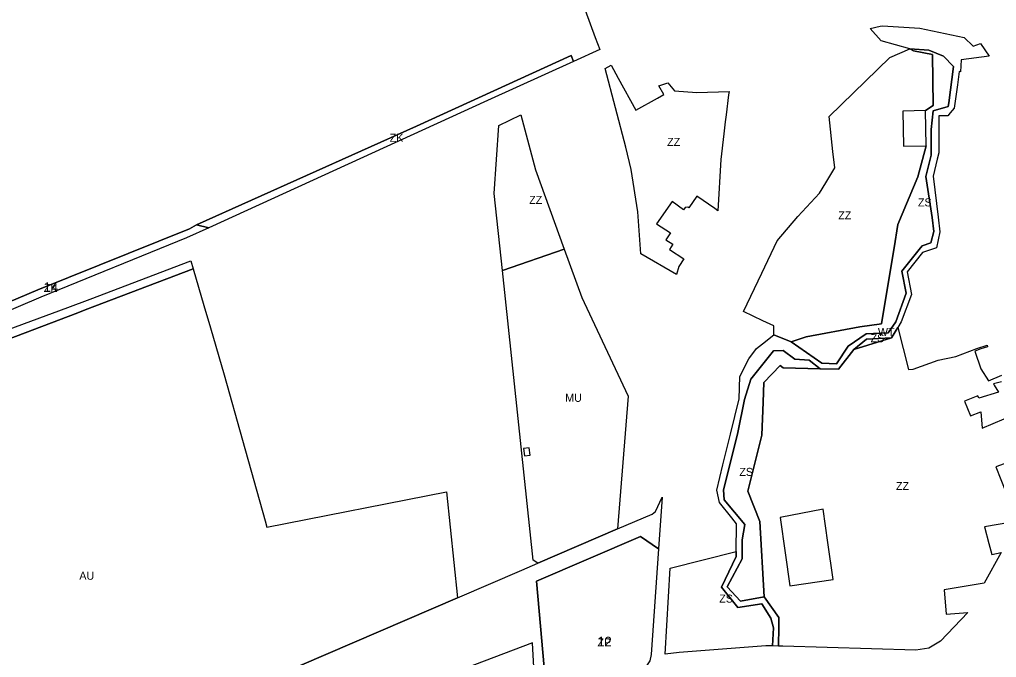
# Model space of a CAD drawing. Extents: x -522079 to -518833, y -1142398 to -1139961.
# Drawn here: x -521001 to -520390, y -1141186 to -1140787 of the extents above; entities that cross this region are included whole.
import ezdxf

# ---------------------------------------------------------------- set-up
doc = ezdxf.new("R2010")
doc.units = 0
for name, color, linetype in [('90640013', 7, 'Continuous'), ('90660013', 7, 'Continuous'), ('90670013', 7, 'Continuous'), ('90680023', 7, 'Continuous'), ('90710013', 7, 'Continuous'), ('90710023', 7, 'Continuous'), ('90750013', 7, 'Continuous'), ('90830013', 7, 'Continuous'), ('ID_navrh', 7, 'Continuous')]:
    doc.layers.add(name, color=color, linetype=linetype)

msp = doc.modelspace()

# ---------------------------------------------------------------- linework, layer by layer
at = {"layer": '90640013'}
msp.add_lwpolyline([(-520536.52, -1140989.65), (-520529.52, -1140984.06), (-520518.62, -1140988.49), (-520499.42, -1141001.88), (-520490.41, -1141002.21), (-520483.03, -1140991.17), (-520471.76, -1140983.46), (-520458.05, -1140982.9), (-520453.28, -1140975.93), (-520446.79, -1140958), (-520449.47, -1140944.32), (-520438.64, -1140930.72), (-520436.87, -1140928.43), (-520431.36, -1140926.59), (-520429.5, -1140919.57), (-520430.59, -1140910.8), (-520434.57, -1140885.18), (-520431.14, -1140872), (-520431.21, -1140855.94), (-520429.98, -1140844.23), (-520420.46, -1140841.58), (-520420.15, -1140839.19), (-520417.22, -1140816.48), (-520423.57, -1140810.07), (-520432.63, -1140806.38), (-520444.45, -1140805.57), (-520462.48, -1140800.42), (-520469.2, -1140792.72), (-520463.08, -1140791.37), (-520461.64, -1140791.05), (-520438.34, -1140792.64), (-520410.6, -1140798.4), (-520404.93, -1140803.86), (-520400.31, -1140802.09), (-520394.93, -1140810.08), (-520412.34, -1140812.28), (-520412.85, -1140819.83), (-520413.68, -1140819.71), (-520414.81, -1140828.01), (-520416.81, -1140842.62), (-520419.27, -1140845.56), (-520420.69, -1140847.27), (-520426.43, -1140847.27), (-520426.37, -1140870.34), (-520427.4, -1140874.32), (-520429.99, -1140884.98), (-520426.8, -1140910.65), (-520425.67, -1140919.72), (-520427.82, -1140929.68), (-520436.62, -1140932.6), (-520446.27, -1140944.76), (-520443.57, -1140958.81), (-520449.86, -1140976.07), (-520451.99, -1140979.48), (-520456.05, -1140986), (-520471.51, -1140986.91), (-520479.55, -1140993.19), (-520489.07, -1141005.5), (-520500.6, -1141005.26), (-520507.31, -1140999.82), (-520516.37, -1140999.34), (-520523.73, -1140993.96), (-520529.65, -1140994.14), (-520543.9, -1141011.82), (-520547.82, -1141024.57), (-520552.06, -1141045.13), (-520556.84, -1141064.48), (-520560.89, -1141080.93), (-520560.53, -1141087.18), (-520547.68, -1141102.49), (-520549.29, -1141112.12), (-520549.23, -1141120.44), (-520549.21, -1141123.97), (-520558.62, -1141141.55), (-520550.27, -1141150.4), (-520535.5, -1141147.72), (-520526.34, -1141160.53), (-520526.38, -1141166.45), (-520526.48, -1141178.44), (-520530.26, -1141178.39), (-520529.73, -1141167.05), (-520531.44, -1141160.96), (-520536.94, -1141152.14), (-520551.87, -1141154.33), (-520562.26, -1141141.67), (-520553, -1141122.43), (-520552.98, -1141119.42), (-520552.84, -1141102.13), (-520555.74, -1141098.46), (-520563.4, -1141088.78), (-520565.18, -1141081.15), (-520561.24, -1141065.24), (-520556.5, -1141046.1), (-520551.07, -1141024.16), (-520550.66, -1141010.15), (-520545.15, -1140999.12), (-520540.36, -1140992.71)], close=True, dxfattribs=at)
at = {"layer": '90660013'}
for points in [[(-520518.62, -1140988.49), (-520509.19, -1140985.26), (-520475.75, -1140979.18), (-520462.25, -1140977.23), (-520456.82, -1140944.51), (-520454.37, -1140929.78), (-520451.95, -1140915.2), (-520439.44, -1140885.49), (-520434.39, -1140866.1), (-520434.81, -1140844.08), (-520430.02, -1140840.87), (-520430.39, -1140809.03), (-520442.16, -1140806.74), (-520444.45, -1140805.57), (-520432.63, -1140806.38), (-520423.57, -1140810.07), (-520417.22, -1140816.48), (-520420.15, -1140839.19), (-520420.46, -1140841.58), (-520429.98, -1140844.23), (-520431.21, -1140855.94), (-520431.14, -1140872), (-520434.57, -1140885.18), (-520430.59, -1140910.8), (-520429.5, -1140919.57), (-520431.36, -1140926.59), (-520436.87, -1140928.43), (-520438.64, -1140930.72), (-520449.47, -1140944.32), (-520446.79, -1140958), (-520453.28, -1140975.93), (-520458.05, -1140982.9), (-520471.76, -1140983.46), (-520483.03, -1140991.17), (-520490.41, -1141002.21), (-520499.42, -1141001.88)], [(-520479.55, -1140993.19), (-520471.51, -1140986.91), (-520456.05, -1140986)], [(-520500.6, -1141005.26), (-520523.55, -1141004.78), (-520525.61, -1141003.28), (-520535.76, -1141013.89), (-520536.12, -1141026.2), (-520537, -1141046.7), (-520545.68, -1141081.75), (-520538.13, -1141100.63), (-520535.5, -1141147.72), (-520550.27, -1141150.4), (-520558.62, -1141141.55), (-520549.21, -1141123.97), (-520549.23, -1141120.44), (-520549.29, -1141112.12), (-520547.68, -1141102.49), (-520560.53, -1141087.18), (-520560.89, -1141080.93), (-520556.84, -1141064.48), (-520552.06, -1141045.13), (-520547.82, -1141024.57), (-520543.9, -1141011.82), (-520529.65, -1140994.14), (-520523.73, -1140993.96), (-520516.37, -1140999.34), (-520507.31, -1140999.82)], [(-520530.26, -1141178.39), (-520534.49, -1141178.34), (-520588.63, -1141182.42), (-520597.46, -1141183.55), (-520594.25, -1141129.86), (-520552.98, -1141119.42), (-520553, -1141122.43), (-520562.26, -1141141.67), (-520551.87, -1141154.33), (-520536.94, -1141152.14), (-520531.44, -1141160.96), (-520529.73, -1141167.05)]]:
    msp.add_lwpolyline(points, close=True, dxfattribs=at)
at = {"layer": '90670013'}
for points in [[(-520434.81, -1140844.08), (-520448.82, -1140844.35), (-520448.4, -1140866.37), (-520434.39, -1140866.1), (-520439.44, -1140885.49), (-520451.95, -1140915.2), (-520454.37, -1140929.78), (-520456.82, -1140944.51), (-520462.25, -1140977.23), (-520475.75, -1140979.18), (-520509.19, -1140985.26), (-520518.62, -1140988.49), (-520529.52, -1140984.06), (-520529.45, -1140978.56), (-520536.34, -1140975.31), (-520548.43, -1140969.6), (-520536.98, -1140945.57), (-520527.38, -1140925.42), (-520514.41, -1140910.27), (-520500.98, -1140895.73), (-520497.04, -1140889.19), (-520491.41, -1140879.85), (-520492.53, -1140869.55), (-520494.89, -1140847.8), (-520456.93, -1140810.9), (-520444.45, -1140805.57), (-520442.16, -1140806.74), (-520430.39, -1140809.03), (-520430.02, -1140840.87)], [(-520634.79, -1140817.77), (-520631.12, -1140815.76), (-520626.71, -1140823.74), (-520615.7, -1140843.89), (-520602.23, -1140836.31), (-520598.3, -1140834.1), (-520601.28, -1140828.55), (-520595.7, -1140826.74), (-520591.61, -1140831.81), (-520577.54, -1140832.73), (-520557.47, -1140832.08), (-520557.73, -1140834.26), (-520559.29, -1140846.65), (-520559.8, -1140851.08), (-520560.66, -1140858.55), (-520562.5, -1140874.6), (-520564.56, -1140906.56), (-520566.38, -1140905.28), (-520577.55, -1140897.54), (-520582.61, -1140904.74), (-520583.16, -1140904.29), (-520584.9, -1140904.6), (-520585.91, -1140906.02), (-520592.91, -1140900.92), (-520602.83, -1140914.7), (-520594.01, -1140920.33), (-520596.85, -1140924.77), (-520592.56, -1140927.47), (-520594.7, -1140930.72), (-520585.74, -1140936.61), (-520588.9, -1140941.38), (-520590.36, -1140946.34), (-520612.5, -1140933.48), (-520614.37, -1140907.34), (-520618.56, -1140880.81), (-520621.9, -1140866.86)], [(-520660.47, -1140930.63), (-520699.09, -1140943.92), (-520704.17, -1140895.93), (-520701.37, -1140853.35), (-520687.49, -1140846.81), (-520678.48, -1140881.15)], [(-520498.69, -1141092.95), (-520525.62, -1141098.2), (-520522.42, -1141120.25), (-520519.42, -1141140.9), (-520492.31, -1141136.96), (-520495.67, -1141113.78)]]:
    msp.add_lwpolyline(points, close=True, dxfattribs=at)
for points in [[(-520374.68, -1141099.98), (-520397.79, -1141103.97), (-520395.09, -1141114.42), (-520393.3, -1141121.36), (-520387.46, -1141120.02), (-520397.97, -1141139.24), (-520423.06, -1141143.4), (-520421.91, -1141158.52), (-520408.18, -1141157.48), (-520425.27, -1141175.41), (-520432.59, -1141179.7), (-520440.68, -1141181.04), (-520523.78, -1141178.47), (-520526.48, -1141178.44), (-520526.38, -1141166.45), (-520526.34, -1141160.53), (-520535.5, -1141147.72), (-520538.13, -1141100.63), (-520545.68, -1141081.75), (-520537, -1141046.7), (-520536.12, -1141026.2), (-520535.76, -1141013.89), (-520525.61, -1141003.28), (-520523.55, -1141004.78), (-520500.6, -1141005.26), (-520489.07, -1141005.5), (-520479.55, -1140993.19), (-520456.05, -1140986), (-520451.99, -1140979.48), (-520445.36, -1141005.71), (-520442.37, -1141005.47), (-520426.91, -1140999.86), (-520415.87, -1140997.65), (-520402.73, -1140992.69), (-520396.26, -1140990.46), (-520396.06, -1140991.53), (-520400.05, -1140992.89), (-520403.95, -1140994.2), (-520400.21, -1141005.43), (-520395.43, -1141012.8), (-520386.94, -1141009.33)], [(-520387.31, -1141013.36), (-520392.22, -1141014.66), (-520391.74, -1141015.46), (-520389.08, -1141019.93), (-520401.32, -1141023.68), (-520401.95, -1141022.11), (-520410.31, -1141025.45), (-520406.62, -1141034.69), (-520400.21, -1141032.13), (-520399.24, -1141042.3), (-520385.48, -1141036.63)], [(-520380.42, -1141062.83), (-520390.79, -1141066.51), (-520384.48, -1141082.4)]]:
    msp.add_lwpolyline(points, dxfattribs=at)
at = {"layer": '90680023'}
msp.add_lwpolyline([(-520601.54, -1141117.64), (-520606.07, -1141183.78), (-520607.02, -1141187.64), (-520665.65, -1141273.94), (-520677.78, -1141138.02), (-520612.8, -1141110.04)], close=True, dxfattribs=at)
at = {"layer": '90710013'}
msp.add_lwpolyline([(-520882.47, -1140917.37), (-520890.08, -1140915.49), (-520752.69, -1140853.85), (-520656.02, -1140809.72), (-520654.73, -1140813.47), (-520708.35, -1140837.86)], close=True, dxfattribs=at)
for points in [[(-520890.16, -1141218.54), (-520727.16, -1141148.38), (-520686.99, -1141131.09), (-520676.95, -1141126.77), (-520627.13, -1141105.32), (-520605.48, -1141096), (-520603.47, -1141094.45), (-520599.33, -1141085.41), (-520601.54, -1141117.64), (-520612.8, -1141110.04), (-520677.78, -1141138.02), (-520665.65, -1141273.94)], [(-520674.18, -1141286.49), (-520680.34, -1141176.38), (-520746.65, -1141201.66)]]:
    msp.add_lwpolyline(points, dxfattribs=at)
at = {"layer": '90710023'}
msp.add_lwpolyline([(-521082.3, -1140995.42), (-520989.26, -1140956.04), (-520894.6, -1140917.89), (-520890.08, -1140915.49), (-520882.47, -1140917.37), (-520896.33, -1140923.45), (-520987.34, -1140960.66), (-521077.97, -1140999.02), (-521081.12, -1140996.97)], close=True, dxfattribs=at)
msp.add_lwpolyline([(-521177.35, -1141247.92), (-521225.53, -1141078.04), (-521222.3, -1141071.25), (-521191.96, -1141057.88), (-521155.63, -1141041.85), (-521112.83, -1141022.98), (-521082.18, -1141009.47), (-521026.59, -1140987.63), (-520970.5, -1140967.09), (-520956.56, -1140961.79), (-520893.74, -1140937.98), (-520892.3, -1140942.89), (-520959.78, -1140968.46), (-520964.29, -1140970.32), (-521085.77, -1141016.42), (-521111.47, -1141027.75), (-521154.28, -1141046.62), (-521190.59, -1141062.63), (-521216.29, -1141073.97), (-521143.42, -1141331.19)], dxfattribs=at)
at = {"layer": '90750013'}
msp.add_lwpolyline([(-520652.69, -1140766.32), (-520641.11, -1140798.37), (-520638.22, -1140805.93), (-520654.73, -1140813.47), (-520656.02, -1140809.72), (-520752.69, -1140853.85), (-520890.08, -1140915.49), (-520894.6, -1140917.89), (-520989.26, -1140956.04), (-521082.3, -1140995.42)], dxfattribs=at)
msp.add_lwpolyline([(-520727.16, -1141148.38), (-520890.16, -1141218.54), (-520895.96, -1141221.04), (-521038.45, -1141284.46), (-521081.35, -1141303.56), (-521117.38, -1141319.6), (-521143.42, -1141331.19), (-521216.29, -1141073.97), (-521190.59, -1141062.63), (-521154.28, -1141046.62), (-521111.47, -1141027.75), (-521085.77, -1141016.42), (-520964.29, -1140970.32), (-520959.78, -1140968.46), (-520892.3, -1140942.89), (-520888.93, -1140954.41), (-520885.58, -1140965.84), (-520881.52, -1140979.72), (-520872.93, -1141009.05), (-520861.45, -1141049.84), (-520847.24, -1141100.33), (-520846.14, -1141104.23), (-520733.88, -1141082.24)], close=True, dxfattribs=at)
at = {"layer": '90830013'}
for points in [[(-520649.51, -1140960.76), (-520648.03, -1140963.9), (-520620.51, -1141022.34), (-520627.13, -1141105.32), (-520676.95, -1141126.77), (-520679.92, -1141124.76), (-520699.09, -1140943.92), (-520660.47, -1140930.63)], [(-520681.75, -1141059.18), (-520682.32, -1141054.61), (-520685.9, -1141055.06), (-520685.33, -1141059.63)]]:
    msp.add_lwpolyline(points, close=True, dxfattribs=at)

# ---------------------------------------------------------------- texts
at = {"layer": '90640013'}
msp.add_text('WT', height=5, rotation=360, dxfattribs=at).set_placement((-520464.453, -1140984.745))
at = {"layer": '90660013'}
for rotation, p in [(360, (-520439.426, -1140903.89)), (0, (-520469.037, -1140988.7)), (360, (-520551.023, -1141072.18)), (0, (-520563.595, -1141151.319))]:
    msp.add_text('ZS', height=5, rotation=rotation, dxfattribs=at).set_placement(p)
at = {"layer": '90670013'}
for rotation, p in [(0, (-520596.13, -1140866.136)), (0, (-520682.32, -1140902.332)), (0, (-520489.225, -1140911.962)), (360, (-520453.195, -1141081.034))]:
    msp.add_text('ZZ', height=5, rotation=rotation, dxfattribs=at).set_placement(p)
at = {"layer": '90680023'}
msp.add_text('ZP', height=5, rotation=360, dxfattribs=at).set_placement((-520639.66, -1141178.645))
at = {"layer": '90710013'}
msp.add_text('ZK', height=5, rotation=0, dxfattribs=at).set_placement((-520769.449, -1140863.545))
at = {"layer": '90710023'}
msp.add_text('ZK', height=5, rotation=360, dxfattribs=at).set_placement((-520985.571, -1140957.255))
at = {"layer": '90750013'}
msp.add_text('AU', height=5, rotation=0, dxfattribs=at).set_placement((-520963.367, -1141137.04))
at = {"layer": '90830013'}
msp.add_text('MU', height=5, rotation=0, dxfattribs=at).set_placement((-520659.8, -1141025.929))
at = {"layer": 'ID_navrh'}
for s, p in [('14', (-520985.571, -1140957.255)), ('12', (-520639.66, -1141178.645))]:
    msp.add_text(s, height=6, rotation=0, dxfattribs=at).set_placement(p)

doc.saveas('drawing.dxf')
